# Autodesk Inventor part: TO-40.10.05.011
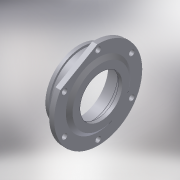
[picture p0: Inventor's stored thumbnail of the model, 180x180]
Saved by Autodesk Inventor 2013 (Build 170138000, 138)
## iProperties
Shininess: 25.0
Angle Display Precision: 2
Document Length Units: 11269
Document Angle Units: 11279
Document Time Units: 11290
Document Mass Units: 11283
Document Length Units Precision: 3
Document Angle Units Precision: 2
Created: 2002-05
Part Number: TO-40.10.05.011
Description: Крышка
Document SubType Name: Modeling
Designer: SaAlex
Density: 1 g/cm^3
Material: Generic
Mass: 473.159 g
Surface Area: 1047.81 cm^2
Volume: 473.159 cm^3
Density: 0.0
Volumn: 0.0
Area: 0.0
PropertySet Name: Model Information
Control State: 0
Master: False
Checked Out: True
Last Check In Date: 2008-10-15
Checked Out Date: 2008-10-15
Author: SaAlex
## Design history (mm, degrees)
sketch "Sketch1"
  geometry: L1 (17.5, 62.5)-(17.5, 50.5); L2 (4.5, 62.5)-(17.5, 62.5); L3 (4.5, 62.5)-(2.5, 63.655); L4 (2.5, 70)-(2.5, 63.655); L5 (-26.5, 70)-(2.5, 70); L6 (-26.5, 80)-(-26.5, 70); L7 (-26.5, 80)-(-18.5, 80); L8 (-18.5, 80)-(-18.5, 75); L9 (-18.5, 75)-(-11.5, 75); L10 (-11.5, 80)-(-11.5, 75); L11 (-11.5, 80)-(7.5, 80); L12 (7.5, 105)-(7.5, 80); L13 (7.5, 105)-(19.5, 105); L14 (19.5, 105)-(19.5, 77); L15 (19.5, 77)-(26.5, 68); L16 (26.5, 68)-(26.5, 50.5); L17 (17.5, 50.5)-(26.5, 50.5); L18 (-23.5, 0)-(26.5, 0); L19 (-23.5, 0)-(26.5, 0)
  constraints: 38 end point, 8 horizontal, 8 vertical, 1 collinear, 1 other
  dimensions: "d1" = 53 horizontal distance of L5.start L16.end; "d3" = 12 distance of L12.start L13.end; "d5" = 34 distance of L11.end L6.start; "d7" = 8 distance of L6.start L7.end; "d9" = 7 distance of L8.end L9.end; "d11" = 50.5 distance of L16.end L18.end; "d13" = 68 distance of L15.end L18.end; "d15" = 77 vertical distance of L14.end L18.end; "d17" = 62.5 vertical distance of L1.start L18.end; "d19" = 70 vertical distance of L5.start L18.start; "d21" = 29 distance of L5.start L4.start; "d23" = 15 horizontal distance of L4.start L1.end; "d25" = 80 vertical distance of L6.start L18.start; "d27" = 75 vertical distance of L9.end L18.start; "d29" = 2 horizontal distance of L2.start L3.end; "d31" = 30 deg angle of L2 L3; "d33" = 105 vertical distance of L12.start L18.start
revolve "RevolutionFull1" sketch "Sketch1" stored, may be unused: angle "d34" = 360 deg
node "WorkAxis1"
sketch "Sketch2"
  geometry: C1 r 6.5 at (-92.5, 0); C2 r 50.5 at (0, 0) reference
  constraints: 1 centre point
  dimensions: "d38" = 13 diameter of C1; "d40" = 92.5 distance of C1.centre C2.centre
extrude "ExtrusionThru1" cut sketch "Sketch2" stored distance "d42" = 0.13; taper "d43" = 0 deg
pattern_circular "PolarArray1" dims angle "d46" = 360 deg
sketch "Sketch3"
  geometry: C1 r 15 at (-50, -29); C2 r 50.5 at (0, 0) reference
  constraints: 1 centre point
  dimensions: "d48" = 30 diameter of C1; "d50" = 29 vertical distance of C1.centre C2.centre; "d52" = 50 horizontal distance of C1.centre C2.centre
extrude "ExtrusionBlind1" cut sketch "Sketch3" distance "d53" = 31; taper "d54" = 0 deg
sketch "Sketch4"
  geometry: L1 (116.675, 18.088)-(34.007, -125.098); L2 (135.468, 234.638)-(0, 0); L3 (0, -241.183)-(0, 0); C1 r 105 at (0, 0) reference; C2 r 50.5 at (0, 0) reference; A1 r 105 centre (19.277, -21.136) between (34.007, -125.098) and (116.675, 18.088)
  constraints: 6 end point, 2 point on circle, 1 centre point, 1 parallel, 1 vertical
  dimensions: "d56" = 105 radius of A1; "d58" = 30 deg angle of L3 L2; "d60" = 92 distance between parallel lines of L2 L1; "d62" = 165.336 distance of L1.start L1.end
extrude "ExtrusionThru2" cut sketch "Sketch4" stored distance "d63" = 0.13; taper "d64" = 0 deg
body "Solid1"
other parameters: "d0" = 53 (derived), "d2" = 12 (derived), "d4" = 34 (derived), "d6" = 8 (derived), "d8" = 7 (derived), "d10" = 50.5 (derived), "d12" = 68 (derived), "d14" = 77 (derived), "d16" = 62.5 (derived), "d20" = 29 (derived), "d22" = 15 (derived), "d26" = 75 (derived), "d28" = 2 (derived), "d30" = 30 deg (derived), "d32" = 105 (derived), "d35" = 0, "d36" = 0, "d37" = 13 (derived), "d39" = 92.5 (derived), "d41" = 0 (derived), "d49" = 29 (derived), "d55" = 105 (derived), "d57" = 30 deg (derived), "d59" = 92 (derived), "d61" = 165.336 (derived)
